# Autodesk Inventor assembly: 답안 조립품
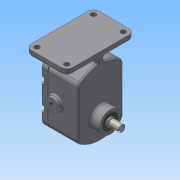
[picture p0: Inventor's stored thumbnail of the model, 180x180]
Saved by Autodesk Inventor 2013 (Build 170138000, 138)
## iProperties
Created: 2019-03
Part Number: 답안 조립품
Document SubType Name: Assembly
Designer: Administrator
Author: Administrator
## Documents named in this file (11)
- C:\Users\Administrator\Desktop\490307V1041\답안 조립품.iam
- C:\Users\Administrator\Desktop\490307V1041\개스킷.ipt
- C:\Users\Administrator\Desktop\490307V1041\메인축.ipt
- C:\Users\Administrator\Desktop\490307V1041\베어링부시.ipt
- C:\Users\Administrator\Desktop\490307V1041\본체.ipt
- C:\Users\Administrator\Desktop\490307V1041\볼트 M5.ipt
- C:\Users\Administrator\Desktop\490307V1041\서브축.ipt
- C:\Users\Administrator\Desktop\490307V1041\스퍼기어.ipt
- C:\Users\Administrator\Desktop\490307V1041\오일 실 16 28 7.ipt
- C:\Users\Administrator\Desktop\490307V1041\커버.ipt
- C:\Users\Administrator\Desktop\490307V1041\키 6 x 6 x 18.ipt
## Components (1 placed, 1 different names)
1. 개스킷:1
